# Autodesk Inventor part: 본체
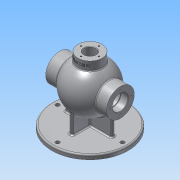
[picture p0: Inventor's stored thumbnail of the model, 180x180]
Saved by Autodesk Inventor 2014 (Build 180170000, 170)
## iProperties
Created: 2020-08
Part Number: 본체
Material: 알루미늄 6061
Document SubType Name: Modeling
Designer: net
Density: 2.71 g/cm^3
Appearance: 알루미늄 - 평지
Mass: 1759.18 g
Surface Area: 1342.58 cm^2
Volume: 649.145 cm^3
Author: net
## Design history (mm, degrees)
sketch "스케치1"
  geometry: L1 (0, 0)-(0, 106); A1 r 53 centre (0, 53) between (0, 106) and (0, 0)
  constraints: 2 end point, 2 point on circle, 1 centre point, 1 midpoint, 1 vertical
  dimensions: "d0" = 106 distance of L1.start L1.end
revolve "회전1" sketch "스케치1" stored, may be unused: angle "d1" = 90 deg
sketch "스케치2"
  geometry: L1 (-68, 53)-(68, 53); L2 (-68, 53)-(-68, 84); L3 (-68, 84)-(68, 84); L4 (68, 84)-(68, 53); 3 further points
  constraints: 8 end point, 3 perpendicular, 1 coincident, 1 horizontal, 1 midpoint, 1 vertical alignment
  dimensions: "d2" = 136 distance of L1.start L1.end; "d3" = 62 diameter of L3 L1
revolve "회전2" sketch "스케치2" stored, may be unused: angle "d4" = 90 deg
node "작업 평면1"
sketch "스케치3"
  geometry: C1 r 85 at (0, 53); A1 r 53 centre (0, 53) between (-42.988, 22) and (-42.988, 84) reference; 1 further point
  constraints: 1 centre point, 1 coincident
  dimensions: "d6" = 170 diameter of C1
extrude "돌출1" join sketch "스케치3" distance "d7" = 10; taper "d8" = 0 deg
node "작업 평면2"
sketch "스케치4"
  geometry: C1 r 85 at (0, 0) reference; C2 r 27 at (0, 0); 1 further point
  constraints: 1 centre point, 1 coincident
  dimensions: "d10" = 54 diameter of C2
extrude "돌출2" join sketch "스케치4" stored distance "d11" = 10; taper "d12" = 0 deg
node "작업 평면3"
sketch "스케치5"
  geometry: L1 (-68, 31)-(-68, -31) reference; L2 (68, 31)-(68, -31) reference; L3 (-68, 0)-(68, 0); L4 (-68, 17.5)-(-39.278, 17.5); L5 (39.278, 17.5)-(68, 17.5); A1 r 43 centre (0, 0) between (39.278, 17.5) and (-39.278, 17.5); 1 further point
  constraints: 6 end point, 2 collinear, 2 midpoint, 2 point on circle, 2 point on line, 1 centre point, 1 coincident, 1 horizontal alignment, 1 parallel
  dimensions: "d14" = 86 diameter of A1; "d15" = 35 diameter of L4 L3
revolve "회전3" sketch "스케치5" stored, may be unused: angle "d16" = 90 deg
sketch "스케치6"
  geometry: L1 (85, -75)-(-85, -75) reference; L2 (-52, -75)-(-52, -31); L3 (52, -75)-(52, -31); L4 (-42.988, -31)-(-68, -31) reference; L5 (68, -31)-(42.988, -31) reference; L6 (-52, -31)-(-52, -23.944); L7 (-52, -23.944)-(-41.656, -23.944); L8 (52, -31)-(52, -23.944); L9 (52, -23.944)-(41.656, -23.944); A1 r 53 centre (0, 0) between (42.988, 31) and (42.988, -31) reference; A2 r 48.048 centre (0, 0) between (-41.656, -23.944) and (41.656, -23.944); 1 further point
  constraints: 12 end point, 5 perpendicular, 4 point on line, 2 point on circle, 1 centre point, 1 coincident, 1 parallel
  dimensions: "d17" = 104 distance of L3.start L2.start; "d19" = 52 horizontal distance of L2.start point (0, 0); "d20" = 96.09501 diameter of A2; "d21" = 10.34385 distance of L6.end L7.end; "d22" = 10.34385 distance of L8.end L9.end
extrude "돌출3" join sketch "스케치6" stored distance "d23" = 8; taper "d24" = 0 deg
sketch "스케치7"
  geometry: L1 (138, -75)-(-32, -75) reference; L2 (10, -30.984)-(10, -75); L3 (96, -30.984)-(96, -75); A1 r 53 centre (53, 0) between (26, 45.607) and (80, 45.607) reference; 1 further point
  constraints: 4 end point, 2 perpendicular, 2 point on circle, 2 point on line, 1 parallel
  dimensions: "d25" = 86 distance of L3.end L2.end
feature "리브1" sketch "스케치7" dims "d26" = 1, "d27" = 8, "d28" = 0, "d29" = 0, "d30" = 1, "d31" = 1
sketch "스케치8"
  geometry: L1 (138, -75)-(-32, -75) reference; L2 (10, -30.984)-(10, -75); A1 r 53 centre (53, 0) between (26, 45.607) and (80, 45.607) reference; 1 further point
  constraints: 2 end point, 1 perpendicular, 1 point on circle, 1 point on line
  dimensions: "d32" = 43 horizontal distance of L2.end A1.centre
feature "리브2" sketch "스케치8" dims "d33" = 1, "d34" = 8, "d35" = 0, "d36" = 0, "d37" = 1, "d38" = 1
hole "구멍1" diameter "d41" = 26; stored, may be unused: countersink angle "d45" = 90 deg, drill point angle "d47" = 118 deg; dims "d39" = 10, "d40" = 10, "d42" = 6, "d43" = 4, "d44" = 2, "d46" = 8
node "작업 평면4"
sketch "스케치9"
  geometry: L1 (-27, 65)-(-27, 45.607) reference; 2 further points
  constraints: 1 other
  dimensions: "d49" = 27 distance from line of L1 point (0, 56); "d50" = 9 vertical distance of point (0, 56) L1.start
feature "엠보싱1" sketch "스케치9" dims "d0" = 106, "d51" = 0.5, "d52" = 0
sketch "스케치10" dims "d53" = 40
  geometry: C1 r 27 at (0, 0) reference; 3 further points
  constraints: 2 vertical alignment, 1 coincident, 2 other
hole "구멍2" sketch "스케치10" at (0, 20) diameter "d54" = 3.242; stored, may be unused: countersink angle "d58" = 90 deg, drill point angle "d60" = 118 deg; dims "d55" = 12, "d56" = 4, "d57" = 2, "d59" = 15
sketch "스케치11" dims "d64" = 48
  geometry: C1 r 31 at (0, 0) reference; 3 further points
  constraints: 2 horizontal alignment, 1 coincident, 2 other
hole "구멍3" sketch "스케치11" at (24, 0) diameter "d65" = 3.242; stored, may be unused: countersink angle "d69" = 90 deg, drill point angle "d71" = 118 deg; dims "d66" = 12, "d67" = 4, "d68" = 2, "d70" = 15
node "작업 평면5"
sketch "스케치12" dims "d75" = 145
  geometry: C1 r 85 at (0, 0) reference; 3 further points
  constraints: 2 vertical alignment, 1 coincident, 2 other
hole "구멍4" sketch "스케치12" at (0, 72.5) diameter "d76" = 9; stored, may be unused: countersink angle "d80" = 90 deg, drill point angle "d82" = 118 deg; dims "d77" = 12, "d78" = 4, "d79" = 2, "d81" = 15
fillet "모깎기1" dims "d90" = 3
fillet "모깎기2" dims "d91" = 3
fillet "모깎기3" dims "d92" = 3
fillet "모깎기4" dims "d93" = 3
fillet "모깎기5" dims "d94" = 3
chamfer "모따기1" distance "d95" = 1; stored, may be unused: second distance "d96" = 2, angle "d97" = 45 deg
fillet "모깎기6" dims "d98" = 3
node "작업 평면6"
sketch "스케치14"
  geometry: L1 (68, -18.5)-(68, 18.5) reference; L2 (39.278, -17.5)-(39.278, 17.5) reference; L3 (39.278, 0)-(68, 0); L4 (52, 0)-(52, 2.639); L5 (52, 2.639)-(52, 18.5); L6 (52, 18.5)-(50.25, 18.5); L7 (50.25, 18.5)-(50.25, 0); 1 further point
  constraints: 10 end point, 4 perpendicular, 2 midpoint, 2 point on line
  dimensions: "d100" = 16 distance between parallel lines of L1 L5; "d102" = 1.75 distance of L5.end L6.end; "d103" = 37 diameter of L6 L3
revolve "회전5" sketch "스케치14" stored, may be unused: angle "d104" = 90 deg
node "솔리드1"
pattern_circular "원형 패턴1" dims angle "d62" = 360 deg
pattern_circular "원형 패턴2" dims angle "d73" = 360 deg
mirror "대칭1"
pattern_circular "원형 패턴3" dims angle "d84" = 360 deg
node "투영된 루프1"
other parameters: "d5" = -85, "d13" = 53, "d48" = -27, "d99" = 53
